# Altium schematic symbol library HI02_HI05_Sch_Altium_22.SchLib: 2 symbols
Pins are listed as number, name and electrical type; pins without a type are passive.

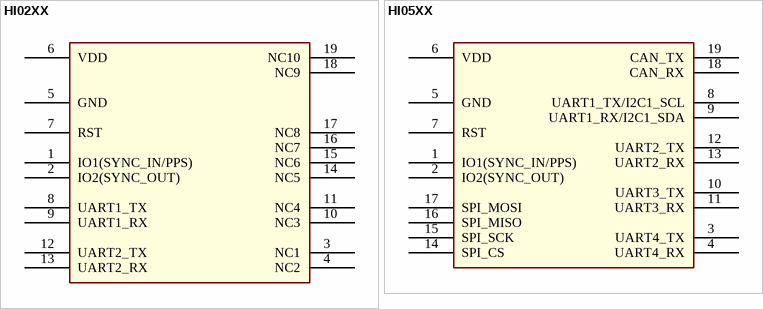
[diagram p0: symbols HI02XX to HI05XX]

## HI02XX
designator U?
pins: 1 IO1(SYNC_IN/PPS), 2 IO2(SYNC_OUT), 3 NC1, 4 NC2, 5 GND, 6 VDD, 7 RST, 8 UART1_TX, 9 UART1_RX, 10 NC3, 11 NC4, 12 UART2_TX, 13 UART2_RX, 14 NC5, 15 NC6, 16 NC7, 17 NC8 (power), 18 NC9 (power), 19 NC10 (power)

## HI05XX
designator U?
pins: 1 IO1(SYNC_IN/PPS), 2 IO2(SYNC_OUT), 3 UART4_TX, 4 UART4_RX, 5 GND, 6 VDD, 7 RST, 8 UART1_TX/I2C1_SCL, 9 UART1_RX/I2C1_SDA, 10 UART3_TX, 11 UART3_RX, 12 UART2_TX, 13 UART2_RX, 14 SPI_CS, 15 SPI_SCK, 16 SPI_MISO, 17 SPI_MOSI (power), 18 CAN_RX (power), 19 CAN_TX (power)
